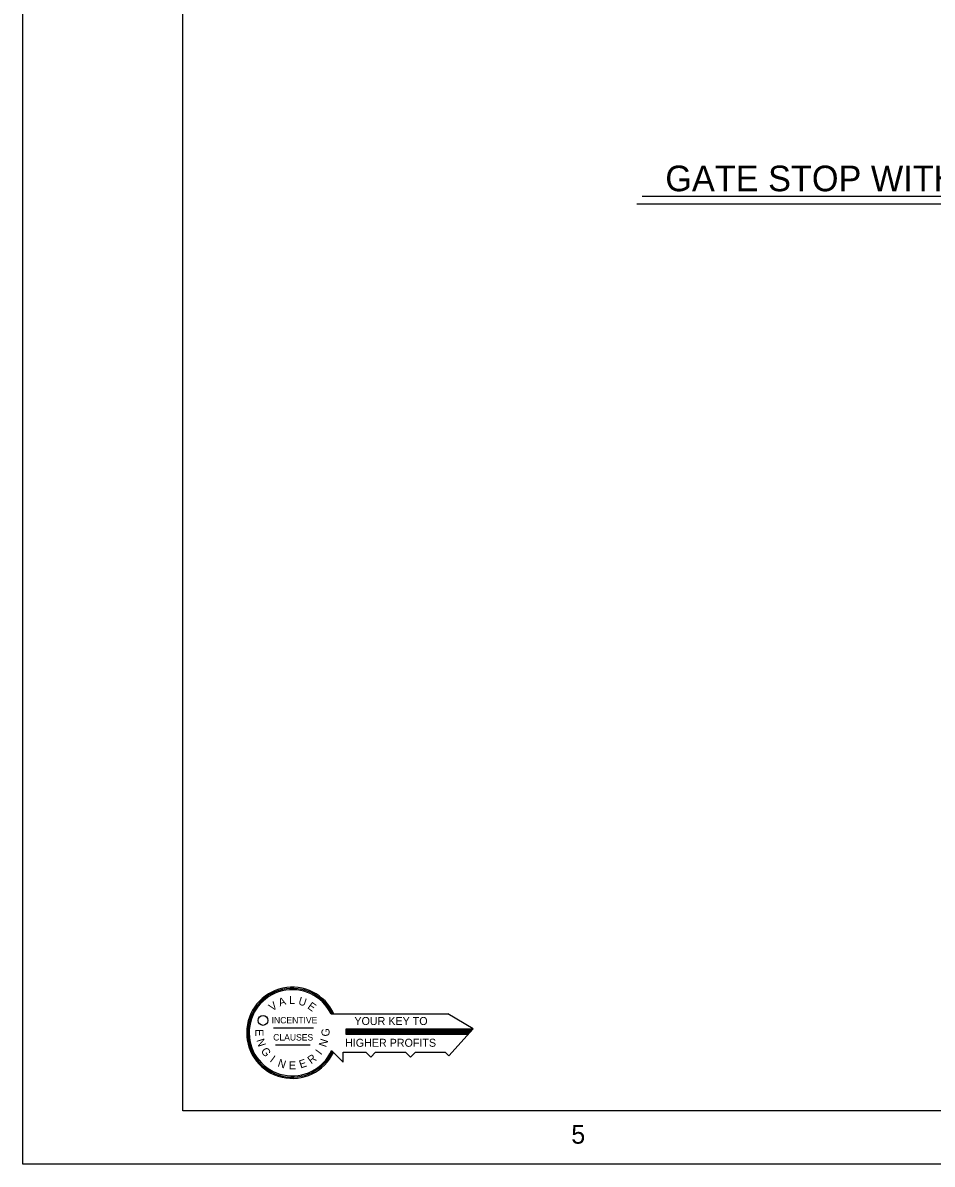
# Model space of a CAD drawing. Extents: x 0.1 to 13.5, y 0.1 to 9.5.
# Drawn here: x 0.125 to 2.965, y 0.125 to 3.691 of the extents above; entities that cross this region are included whole.
import ezdxf

# ---------------------------------------------------------------- set-up
doc = ezdxf.new("R2010")
doc.units = 0
for name, color, linetype in [('Level 1', 7, 'Continuous'), ('Level 2', 7, 'Continuous'), ('Level 25', 7, 'Continuous')]:
    doc.layers.add(name, color=color, linetype=linetype)

msp = doc.modelspace()

# ---------------------------------------------------------------- linework, layer by layer
at = {"layer": 'Level 1'}
for p, q in [((1.0875, 0.5948), (1.4518, 0.5948)), ((1.5313, 0.5478), (1.4518, 0.5948)), ((0.9075, 0.551), (1.0323, 0.551)), ((1.5303, 0.5465), (1.1338, 0.5465)), ((1.1338, 0.5465), (1.1338, 0.531)), ((1.5263, 0.5423), (1.1338, 0.5423)), ((1.5228, 0.5383), (1.1338, 0.5383)), ((1.5313, 0.5478), (1.4555, 0.463)), ((1.519, 0.534), (1.1338, 0.534)), ((1.1338, 0.531), (1.5163, 0.531)), ((0.914, 0.4983), (1.022, 0.4983)), ((1.0893, 0.4798), (1.1255, 0.4435)), ((1.1255, 0.4435), (1.1255, 0.4748)), ((1.1255, 0.4748), (1.1958, 0.4748)), ((1.1958, 0.4748), (1.2113, 0.4593)), ((1.2113, 0.4593), (1.2268, 0.4748)), ((1.2268, 0.4748), (1.3198, 0.4748)), ((1.3198, 0.4748), (1.3353, 0.4593)), ((1.3353, 0.4593), (1.3508, 0.4748)), ((1.3508, 0.4748), (1.4438, 0.4748)), ((1.4438, 0.4748), (1.4555, 0.463))]:
    msp.add_line(p, q, dxfattribs=at)
for points in [[(0.125, 9.4583), (13.4583, 9.4583), (13.4583, 0.125), (0.125, 0.125)], [(0.625, 9.2917), (13.2917, 9.2917), (13.2917, 0.2917), (0.625, 0.2917)]]:
    msp.add_lwpolyline(points, close=True, dxfattribs=at)
msp.add_circle((0.8751, 0.5741), 0.0154, dxfattribs=at)
for radius, start, end in [(0.1425, 24.569, 334.4243), (0.1386, 25.3095, 334.4522), (0.1347, 26.0896, 335.5943)]:
    msp.add_arc((0.9665, 0.5355), radius, start, end, dxfattribs=at)
at = {"layer": 'Level 25'}
for p, q in [((2.0593, 3.1489), (4.9686, 3.1489)), ((2.0429, 3.1251), (4.9923, 3.1251))]:
    msp.add_line(p, q, dxfattribs=at)

# ---------------------------------------------------------------- texts
at = {"layer": 'Level 1'}
for s, rotation, p in [('A', 18.0731, (0.9275, 0.6175)), ('U', 342.1107, (0.9833, 0.6248)), ('V', 35.9204, (0.9043, 0.6015)), ('E', 323.9298, (1.0118, 0.6135)), ('E', 270, (0.8513, 0.5465)), ('G', 90, (1.0828, 0.524)), ('N', 288.0821, (0.854, 0.5125)), ('N', 71.9179, (1.0718, 0.4888)), ('G', 306.0537, (0.8668, 0.4785)), ('I', 323.5836, (0.8945, 0.4468)), ('R', 36.2206, (1.0253, 0.4368)), ('I', 53.5836, (1.0563, 0.4643)), ('N', 341.9179, (0.919, 0.431)), ('E', 18.2241, (0.9925, 0.424))]:
    msp.add_text(s, height=0.025, rotation=rotation, dxfattribs=at).set_placement(p)
for s, height, p in [('L', 0.025, (0.9563, 0.6258)), ('INCENTIVE', 0.02, (0.902, 0.5648)), ('YOUR KEY TO', 0.025, (1.1605, 0.5598)), ('CLAUSES', 0.02, (0.9068, 0.5113)), ('HIGHER PROFITS', 0.025, (1.1313, 0.4918)), ('E', 0.025, (0.9558, 0.4213)), ('5', 0.0584, (1.8378, 0.189))]:
    msp.add_text(s, height=height, dxfattribs=at).set_placement(p)
at = {"layer": 'Level 2'}
msp.add_text('GATE STOP WITH GATE IN CLOSED POSITION', height=0.08, dxfattribs=at).set_placement((2.1314, 3.1647))

doc.saveas('drawing.dxf')
